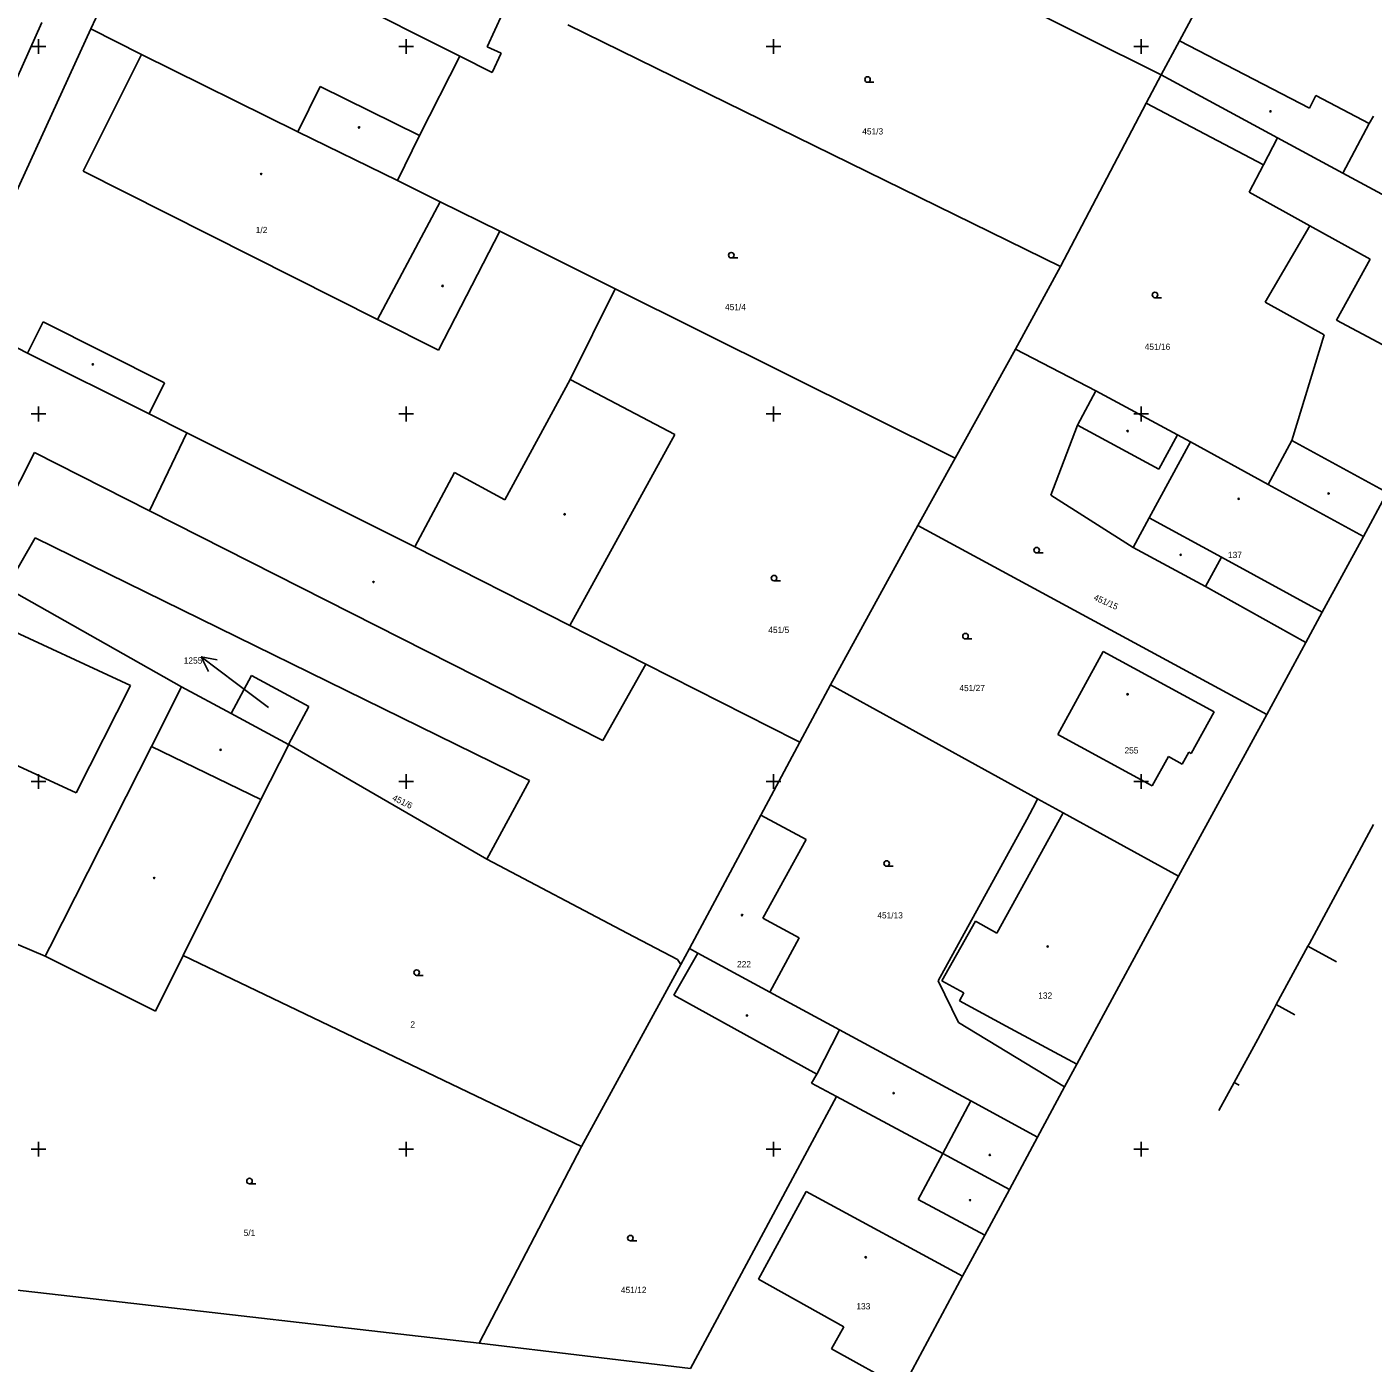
# Model space of a CAD drawing. Extents: x -711081 to -709338, y -1025122 to -1024092.
# Drawn here: x -709575.8 to -709484.2, y -1024464.5 to -1024373.7 of the extents above; entities that cross this region are included whole.
import ezdxf

# ---------------------------------------------------------------- set-up
doc = ezdxf.new("R2010")
doc.units = 0
for name, color, linetype in [('Z_hektometricka_sit', 7, 'Continuous'), ('Z_katastr_cisla_pozemkova', 7, 'Continuous'), ('Z_katastr_cisla_stavebni', 7, 'Continuous'), ('Z_katastr_hranice', 7, 'Continuous'), ('Z_katastr_parcelni_cislo_odkaz', 7, 'Continuous'), ('Z_katastr_vnitrni_kresba', 7, 'Continuous'), ('Z_katastr_znacky_budov', 7, 'Continuous'), ('Z_katastr_znacky_kultur', 7, 'Continuous')]:
    doc.layers.add(name, color=color, linetype=linetype)

msp = doc.modelspace()

# ---------------------------------------------------------------- linework, layer by layer
at = {"layer": 'Z_hektometricka_sit'}
for p, q in [((-709575.5, -1024375), (-709574.5, -1024375)), ((-709575, -1024374.5), (-709575, -1024375.5)), ((-709550.5, -1024375), (-709549.5, -1024375)), ((-709550, -1024374.5), (-709550, -1024375.5)), ((-709525.5, -1024375), (-709524.5, -1024375)), ((-709525, -1024374.5), (-709525, -1024375.5)), ((-709500.5, -1024375), (-709499.5, -1024375)), ((-709500, -1024374.5), (-709500, -1024375.5)), ((-709575, -1024399.5), (-709575, -1024400.5)), ((-709550, -1024399.5), (-709550, -1024400.5)), ((-709525, -1024399.5), (-709525, -1024400.5)), ((-709500, -1024399.5), (-709500, -1024400.5)), ((-709575.5, -1024400), (-709574.5, -1024400)), ((-709550.5, -1024400), (-709549.5, -1024400)), ((-709525.5, -1024400), (-709524.5, -1024400)), ((-709500.5, -1024400), (-709499.5, -1024400)), ((-709575, -1024424.5), (-709575, -1024425.5)), ((-709550, -1024424.5), (-709550, -1024425.5)), ((-709525, -1024424.5), (-709525, -1024425.5)), ((-709500, -1024424.5), (-709500, -1024425.5)), ((-709575.5, -1024425), (-709574.5, -1024425)), ((-709550.5, -1024425), (-709549.5, -1024425)), ((-709525.5, -1024425), (-709524.5, -1024425)), ((-709500.5, -1024425), (-709499.5, -1024425)), ((-709575.5, -1024450), (-709574.5, -1024450)), ((-709575, -1024449.5), (-709575, -1024450.5)), ((-709550.5, -1024450), (-709549.5, -1024450)), ((-709550, -1024449.5), (-709550, -1024450.5)), ((-709525.5, -1024450), (-709524.5, -1024450)), ((-709525, -1024449.5), (-709525, -1024450.5)), ((-709500.5, -1024450), (-709499.5, -1024450)), ((-709500, -1024449.5), (-709500, -1024450.5))]:
    msp.add_line(p, q, dxfattribs=at)
at = {"layer": 'Z_katastr_hranice'}
for p, q in [((-709565.08, -1024360.15), (-709571.44, -1024373.81)), ((-709498.64, -1024376.94), (-709530.8, -1024360.86)), ((-709497.39, -1024374.61), (-709493.08, -1024366.63)), ((-709544.48, -1024375.03), (-709542.85, -1024371.47)), ((-709571.44, -1024373.81), (-709580.49, -1024393.57)), ((-709571.44, -1024373.81), (-709568, -1024375.56)), ((-709538.99, -1024373.54), (-709505.48, -1024389.98)), ((-709543.53, -1024375.46), (-709544.48, -1024375.03)), ((-709497.39, -1024374.61), (-709498.64, -1024376.94)), ((-709488.56, -1024379.21), (-709497.39, -1024374.61)), ((-709568, -1024375.56), (-709557.37, -1024380.8)), ((-709549.08, -1024381.06), (-709546.34, -1024375.66)), ((-709546.34, -1024375.66), (-709544.13, -1024376.78)), ((-709544.13, -1024376.78), (-709543.53, -1024375.46)), ((-709498.64, -1024376.94), (-709499.66, -1024378.87)), ((-709498.64, -1024376.94), (-709490.72, -1024381.22)), ((-709488.11, -1024378.35), (-709488.56, -1024379.21)), ((-709484.48, -1024380.25), (-709488.11, -1024378.35)), ((-709505.48, -1024389.98), (-709499.66, -1024378.87)), ((-709499.66, -1024378.87), (-709491.68, -1024383.06)), ((-709484.2, -1024379.74), (-709484.48, -1024380.25)), ((-709557.37, -1024380.8), (-709550.59, -1024384.13)), ((-709550.59, -1024384.13), (-709549.08, -1024381.06)), ((-709490.72, -1024381.22), (-709486.29, -1024383.61)), ((-709491.68, -1024383.06), (-709492.66, -1024384.92)), ((-709547.67, -1024385.57), (-709550.59, -1024384.13)), ((-709486.29, -1024383.61), (-709474.87, -1024389.78)), ((-709492.66, -1024384.92), (-709488.52, -1024387.21)), ((-709543.63, -1024387.56), (-709547.67, -1024385.57)), ((-709535.77, -1024391.48), (-709543.63, -1024387.56)), ((-709488.52, -1024387.21), (-709491.57, -1024392.39)), ((-709508.55, -1024395.59), (-709505.48, -1024389.98)), ((-709538.83, -1024397.65), (-709535.77, -1024391.48)), ((-709535.77, -1024391.48), (-709512.66, -1024403)), ((-709491.57, -1024392.39), (-709487.55, -1024394.61)), ((-709579.15, -1024394.15), (-709575.74, -1024395.86)), ((-709487.55, -1024394.61), (-709489.74, -1024401.8)), ((-709575.74, -1024395.86), (-709567.48, -1024399.99)), ((-709512.66, -1024403), (-709508.55, -1024395.59)), ((-709503.08, -1024398.43), (-709508.55, -1024395.59)), ((-709531.71, -1024401.39), (-709538.83, -1024397.65)), ((-709503.08, -1024398.43), (-709504.34, -1024400.75)), ((-709497.53, -1024401.42), (-709503.08, -1024398.43)), ((-709567.48, -1024399.99), (-709564.9, -1024401.28)), ((-709564.9, -1024401.28), (-709549.39, -1024409.03)), ((-709538.85, -1024414.39), (-709531.71, -1024401.39)), ((-709504.34, -1024400.75), (-709506.15, -1024405.51)), ((-709496.64, -1024401.9), (-709497.53, -1024401.42)), ((-709491.37, -1024404.79), (-709496.64, -1024401.9)), ((-709489.74, -1024401.8), (-709491.37, -1024404.79)), ((-709515.18, -1024407.59), (-709512.66, -1024403)), ((-709484.88, -1024408.34), (-709491.37, -1024404.79)), ((-709506.15, -1024405.51), (-709500.55, -1024409.07)), ((-709484.88, -1024408.34), (-709483.26, -1024405.35)), ((-709521.13, -1024418.42), (-709515.18, -1024407.59)), ((-709515.18, -1024407.59), (-709491.46, -1024420.43)), ((-709577.18, -1024411.82), (-709575.23, -1024408.42)), ((-709575.23, -1024408.42), (-709541.61, -1024424.92)), ((-709487.68, -1024413.49), (-709484.88, -1024408.34)), ((-709549.39, -1024409.03), (-709538.85, -1024414.39)), ((-709500.55, -1024409.07), (-709495.63, -1024411.74)), ((-709577.18, -1024411.82), (-709565.26, -1024418.55)), ((-709495.63, -1024411.74), (-709488.8, -1024415.54)), ((-709488.8, -1024415.54), (-709487.68, -1024413.49)), ((-709533.69, -1024417.01), (-709538.85, -1024414.39)), ((-709502.59, -1024416.16), (-709505.66, -1024421.79)), ((-709495.03, -1024420.25), (-709502.59, -1024416.16)), ((-709491.46, -1024420.43), (-709488.8, -1024415.54)), ((-709523.49, -1024422.19), (-709533.69, -1024417.01)), ((-709561.9, -1024420.36), (-709560.52, -1024417.79)), ((-709560.52, -1024417.79), (-709556.61, -1024419.9)), ((-709565.26, -1024418.55), (-709561.9, -1024420.36)), ((-709523.22, -1024422.33), (-709521.13, -1024418.42)), ((-709507.04, -1024426.17), (-709521.13, -1024418.42)), ((-709556.61, -1024419.9), (-709558, -1024422.47)), ((-709561.9, -1024420.36), (-709558, -1024422.47)), ((-709497.46, -1024431.44), (-709491.46, -1024420.43)), ((-709496.59, -1024423.1), (-709495.03, -1024420.25)), ((-709505.66, -1024421.79), (-709499.25, -1024425.29)), ((-709557.96, -1024422.49), (-709559.88, -1024426.23)), ((-709558, -1024422.47), (-709557.96, -1024422.49)), ((-709544.5, -1024430.28), (-709557.96, -1024422.49)), ((-709525.87, -1024427.28), (-709523.22, -1024422.33)), ((-709523.22, -1024422.33), (-709523.49, -1024422.19)), ((-709499.25, -1024425.29), (-709498.15, -1024423.3)), ((-709498.15, -1024423.3), (-709497.21, -1024423.82)), ((-709497.21, -1024423.82), (-709496.76, -1024423)), ((-709496.76, -1024423), (-709496.59, -1024423.1)), ((-709541.61, -1024424.92), (-709544.5, -1024430.28)), ((-709559.88, -1024426.23), (-709565.16, -1024436.83)), ((-709507.04, -1024426.17), (-709507.17, -1024426.43)), ((-709505.31, -1024427.12), (-709507.04, -1024426.17)), ((-709530.72, -1024436.35), (-709525.87, -1024427.28)), ((-709522.78, -1024428.93), (-709525.87, -1024427.28)), ((-709507.17, -1024426.43), (-709507.77, -1024427.57)), ((-709502.34, -1024428.75), (-709505.31, -1024427.12)), ((-709507.77, -1024427.57), (-709513.81, -1024438.55)), ((-709488.56, -1024436.01), (-709484.2, -1024427.93)), ((-709525.72, -1024434.29), (-709522.78, -1024428.93)), ((-709497.46, -1024431.44), (-709502.34, -1024428.75)), ((-709544.5, -1024430.28), (-709534.97, -1024435.3)), ((-709504.37, -1024444.22), (-709497.46, -1024431.44)), ((-709523.25, -1024435.63), (-709525.72, -1024434.29)), ((-709534.97, -1024435.3), (-709531.54, -1024437.1)), ((-709574.54, -1024436.88), (-709577.27, -1024435.73)), ((-709531.31, -1024437.44), (-709530.72, -1024436.35)), ((-709530.72, -1024436.35), (-709530.15, -1024436.66)), ((-709525.25, -1024439.32), (-709523.25, -1024435.63)), ((-709490.81, -1024440.17), (-709488.66, -1024436.19)), ((-709488.66, -1024436.19), (-709488.56, -1024436.01)), ((-709486.703, -1024437.259), (-709488.66, -1024436.19)), ((-709567.04, -1024440.62), (-709574.54, -1024436.88)), ((-709565.16, -1024436.83), (-709567.04, -1024440.62)), ((-709565.16, -1024436.83), (-709538.06, -1024449.82)), ((-709531.79, -1024439.53), (-709530.15, -1024436.66)), ((-709531.54, -1024437.1), (-709531.31, -1024437.44)), ((-709530.15, -1024436.66), (-709525.25, -1024439.32)), ((-709538.06, -1024449.82), (-709531.31, -1024437.44)), ((-709513.81, -1024438.55), (-709512.43, -1024441.39)), ((-709522.06, -1024444.89), (-709531.79, -1024439.53)), ((-709525.25, -1024439.32), (-709520.51, -1024441.89)), ((-709492.07, -1024442.51), (-709490.97, -1024440.47)), ((-709490.97, -1024440.47), (-709490.81, -1024440.17)), ((-709490.81, -1024440.17), (-709489.55, -1024440.857)), ((-709520.51, -1024441.89), (-709511.59, -1024446.72)), ((-709512.43, -1024441.39), (-709505.21, -1024445.77)), ((-709493.67, -1024445.47), (-709492.07, -1024442.51)), ((-709505.21, -1024445.77), (-709504.37, -1024444.22)), ((-709522.41, -1024445.51), (-709522.06, -1024444.89)), ((-709520.71, -1024446.42), (-709522.41, -1024445.51)), ((-709493.67, -1024445.47), (-709494.713, -1024447.38)), ((-709493.344, -1024445.649), (-709493.67, -1024445.47)), ((-709530.65, -1024464.91), (-709520.71, -1024446.42)), ((-709507.05, -1024449.18), (-709505.21, -1024445.77)), ((-709511.59, -1024446.72), (-709507.05, -1024449.18)), ((-709508.96, -1024452.74), (-709507.05, -1024449.18)), ((-709545.02, -1024463.2), (-709538.06, -1024449.82)), ((-709510.64, -1024455.86), (-709508.96, -1024452.74)), ((-709512.15, -1024458.65), (-709510.64, -1024455.86)), ((-709582.99, -1024458.83), (-709572.67, -1024460.03)), ((-709516.24, -1024466.26), (-709512.15, -1024458.65)), ((-709572.67, -1024460.03), (-709545.02, -1024463.2)), ((-709545.02, -1024463.2), (-709530.65, -1024464.91))]:
    msp.add_line(p, q, dxfattribs=at)
at = {"layer": 'Z_katastr_parcelni_cislo_odkaz'}
for p, q in [((-709561.54, -1024418.32), (-709563.937, -1024416.514)), ((-709563.937, -1024416.514), (-709562.836, -1024416.717)), ((-709563.937, -1024416.514), (-709563.438, -1024417.517)), ((-709559.36, -1024419.96), (-709561.54, -1024418.32))]:
    msp.add_line(p, q, dxfattribs=at)
at = {"layer": 'Z_katastr_vnitrni_kresba'}
for p, q in [((-709558.43, -1024369.59), (-709546.34, -1024375.66)), ((-709591.53, -1024410.75), (-709574.78, -1024373.38)), ((-709571.96, -1024383.49), (-709568, -1024375.56)), ((-709555.85, -1024377.73), (-709557.37, -1024380.8)), ((-709549.08, -1024381.06), (-709555.85, -1024377.73)), ((-709486.29, -1024383.61), (-709484.48, -1024380.25)), ((-709491.68, -1024383.06), (-709490.72, -1024381.22)), ((-709551.93, -1024393.57), (-709571.96, -1024383.49)), ((-709551.93, -1024393.57), (-709547.67, -1024385.57)), ((-709543.63, -1024387.56), (-709547.78, -1024395.65)), ((-709488.52, -1024387.21), (-709484.42, -1024389.48)), ((-709484.42, -1024389.48), (-709486.72, -1024393.62)), ((-709575.74, -1024395.86), (-709574.69, -1024393.74)), ((-709574.69, -1024393.74), (-709566.42, -1024397.87)), ((-709547.78, -1024395.65), (-709551.93, -1024393.57)), ((-709486.72, -1024393.62), (-709479.11, -1024397.66)), ((-709566.42, -1024397.87), (-709567.48, -1024399.99)), ((-709543.27, -1024405.83), (-709538.83, -1024397.65)), ((-709567.44, -1024406.58), (-709564.9, -1024401.28)), ((-709504.34, -1024400.75), (-709498.79, -1024403.75)), ((-709498.79, -1024403.75), (-709497.53, -1024401.42)), ((-709499.45, -1024407.06), (-709496.64, -1024401.9)), ((-709489.74, -1024401.8), (-709483.26, -1024405.35)), ((-709577.19, -1024406.43), (-709575.28, -1024402.61)), ((-709575.28, -1024402.61), (-709567.44, -1024406.58)), ((-709549.39, -1024409.03), (-709546.7, -1024403.97)), ((-709546.7, -1024403.97), (-709543.27, -1024405.83)), ((-709567.44, -1024406.58), (-709536.61, -1024422.2)), ((-709500.55, -1024409.07), (-709499.45, -1024407.06)), ((-709499.45, -1024407.06), (-709494.53, -1024409.73)), ((-709495.63, -1024411.74), (-709494.53, -1024409.73)), ((-709494.53, -1024409.73), (-709487.68, -1024413.49)), ((-709581.84, -1024412.4), (-709568.73, -1024418.46)), ((-709533.69, -1024417.01), (-709536.61, -1024422.2)), ((-709568.73, -1024418.46), (-709572.44, -1024425.77)), ((-709567.32, -1024422.61), (-709565.26, -1024418.55)), ((-709572.44, -1024425.77), (-709583.37, -1024420.7)), ((-709574.23, -1024436.26), (-709567.32, -1024422.61)), ((-709567.32, -1024422.61), (-709559.88, -1024426.23)), ((-709505.31, -1024427.12), (-709509.82, -1024435.3)), ((-709511.27, -1024434.5), (-709513.56, -1024438.55)), ((-709509.82, -1024435.3), (-709511.27, -1024434.5)), ((-709574.54, -1024436.88), (-709574.23, -1024436.26)), ((-709513.56, -1024438.55), (-709512.06, -1024439.37)), ((-709512.06, -1024439.37), (-709512.36, -1024439.91)), ((-709512.36, -1024439.91), (-709509.17, -1024441.63)), ((-709522.06, -1024444.89), (-709520.51, -1024441.89)), ((-709504.37, -1024444.22), (-709509.17, -1024441.63)), ((-709513.49, -1024450.3), (-709520.71, -1024446.42)), ((-709513.49, -1024450.3), (-709511.59, -1024446.72)), ((-709515.17, -1024453.42), (-709513.49, -1024450.3)), ((-709508.96, -1024452.74), (-709513.49, -1024450.3)), ((-709526.03, -1024458.84), (-709522.79, -1024452.89)), ((-709522.79, -1024452.89), (-709512.15, -1024458.65)), ((-709510.64, -1024455.86), (-709515.17, -1024453.42)), ((-709520.23, -1024462.09), (-709526.03, -1024458.84)), ((-709521.07, -1024463.59), (-709520.23, -1024462.09)), ((-709516.24, -1024466.26), (-709521.07, -1024463.59))]:
    msp.add_line(p, q, dxfattribs=at)
at = {"layer": 'Z_katastr_znacky_budov'}
for centre in [(-709491.202, -1024379.42), (-709553.192, -1024380.51), (-709559.852, -1024383.68), (-709547.512, -1024391.29), (-709571.302, -1024396.63), (-709500.922, -1024401.16), (-709493.362, -1024405.77), (-709487.252, -1024405.41), (-709539.212, -1024406.82), (-709497.312, -1024409.58), (-709552.212, -1024411.43), (-709500.922, -1024419.06), (-709562.612, -1024422.84), (-709567.132, -1024431.56), (-709527.142, -1024434.08), (-709506.352, -1024436.22), (-709526.812, -1024440.91), (-709516.832, -1024446.19), (-709510.292, -1024450.39), (-709511.632, -1024453.47), (-709518.732, -1024457.35)]:
    msp.add_circle(centre, 0.0437, dxfattribs=at)
at = {"layer": 'Z_katastr_znacky_kultur'}
for p, q in [((-709518.608, -1024377.44), (-709518.171, -1024377.44)), ((-709527.878, -1024389.39), (-709527.441, -1024389.39)), ((-709499.058, -1024392.09), (-709498.621, -1024392.09)), ((-709507.108, -1024409.45), (-709506.671, -1024409.45)), ((-709524.968, -1024411.35), (-709524.531, -1024411.35)), ((-709511.948, -1024415.3), (-709511.511, -1024415.3)), ((-709517.308, -1024430.76), (-709516.871, -1024430.76)), ((-709549.278, -1024438.18), (-709548.841, -1024438.18)), ((-709560.648, -1024452.36), (-709560.211, -1024452.36)), ((-709534.738, -1024456.24), (-709534.301, -1024456.24))]:
    msp.add_line(p, q, dxfattribs=at)
for centre in [(-709518.608, -1024377.252), (-709527.878, -1024389.202), (-709499.058, -1024391.902), (-709507.108, -1024409.262), (-709524.968, -1024411.162), (-709511.948, -1024415.112), (-709517.308, -1024430.572), (-709549.278, -1024437.992), (-709560.648, -1024452.172), (-709534.738, -1024456.052)]:
    msp.add_circle(centre, 0.187, dxfattribs=at)

# ---------------------------------------------------------------- texts
at = {"layer": 'Z_katastr_cisla_pozemkova'}
for s, p in [('451/3', (-709518.969, -1024380.99)), ('451/4', (-709528.304, -1024392.94)), ('451/16', (-709499.76, -1024395.64)), ('451/5', (-709525.359, -1024414.9)), ('1255', (-709565.12, -1024416.98)), ('451/27', (-709512.364, -1024418.85)), ('451/13', (-709517.945, -1024434.309)), ('2', (-709549.703, -1024441.73)), ('5/1', (-709561.043, -1024455.91)), ('451/12', (-709535.385, -1024459.789))]:
    msp.add_text(s, height=0.425, dxfattribs=at).set_placement(p)
for s, rotation, p in [('451/15', 336, (-709503.273, -1024412.625)), ('451/6', 334, (-709550.974, -1024426.248))]:
    msp.add_text(s, height=0.425, rotation=rotation, dxfattribs=at).set_placement(p)
at = {"layer": 'Z_katastr_cisla_stavebni'}
for s, p in [('1/2', (-709560.223, -1024387.7)), ('137', (-709494.094, -1024409.799)), ('255', (-709501.133, -1024423.09)), ('222', (-709527.483, -1024437.63)), ('132', (-709506.999, -1024439.77)), ('133', (-709519.369, -1024460.9))]:
    msp.add_text(s, height=0.425, dxfattribs=at).set_placement(p)

doc.saveas('drawing.dxf')
